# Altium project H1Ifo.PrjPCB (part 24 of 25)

## Sheet IfoSqz4B.SchDoc: D1800185
size C; Engineer: Daniel Sigg; DocumentNumber: 9; Revision: 4; SheetNumber: 9; SheetTotal: 10
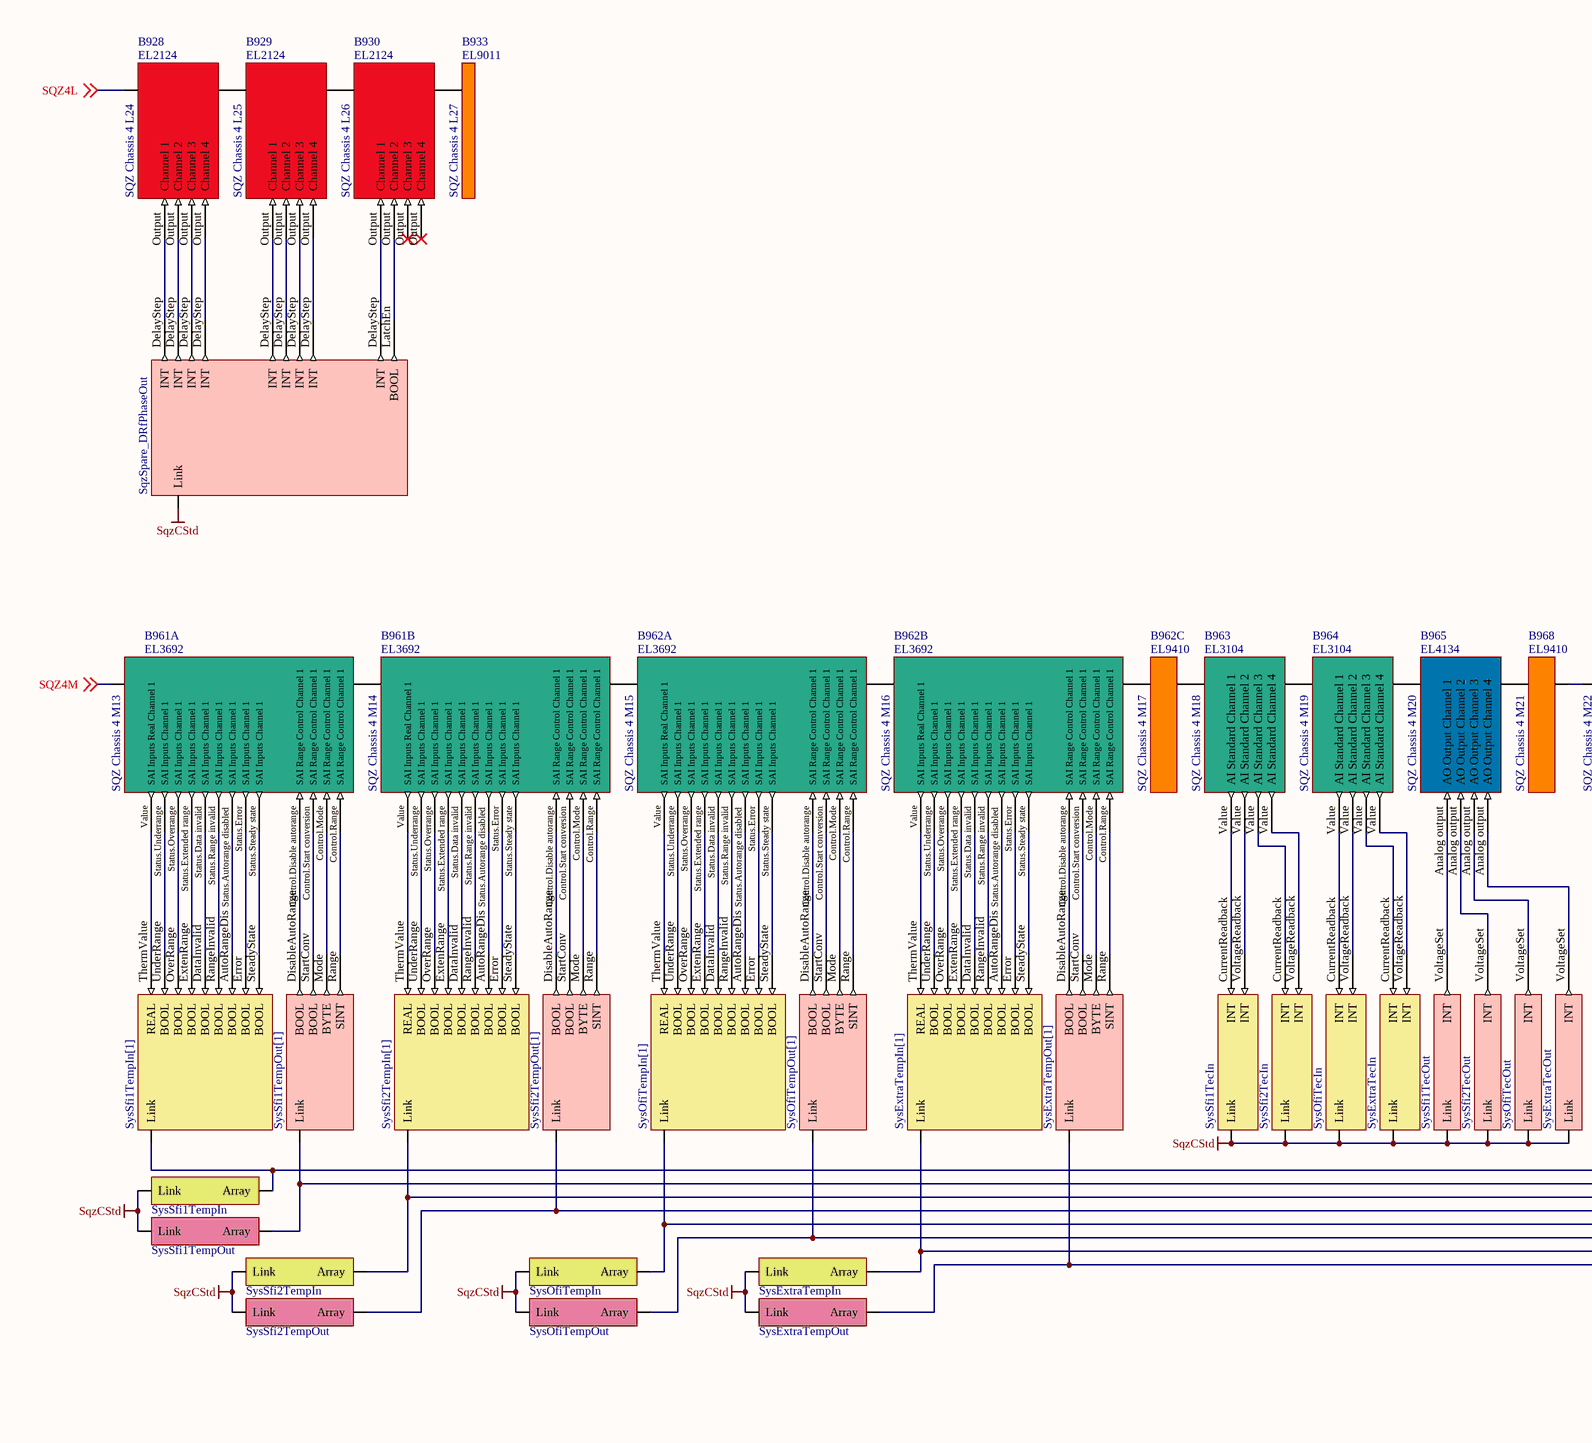
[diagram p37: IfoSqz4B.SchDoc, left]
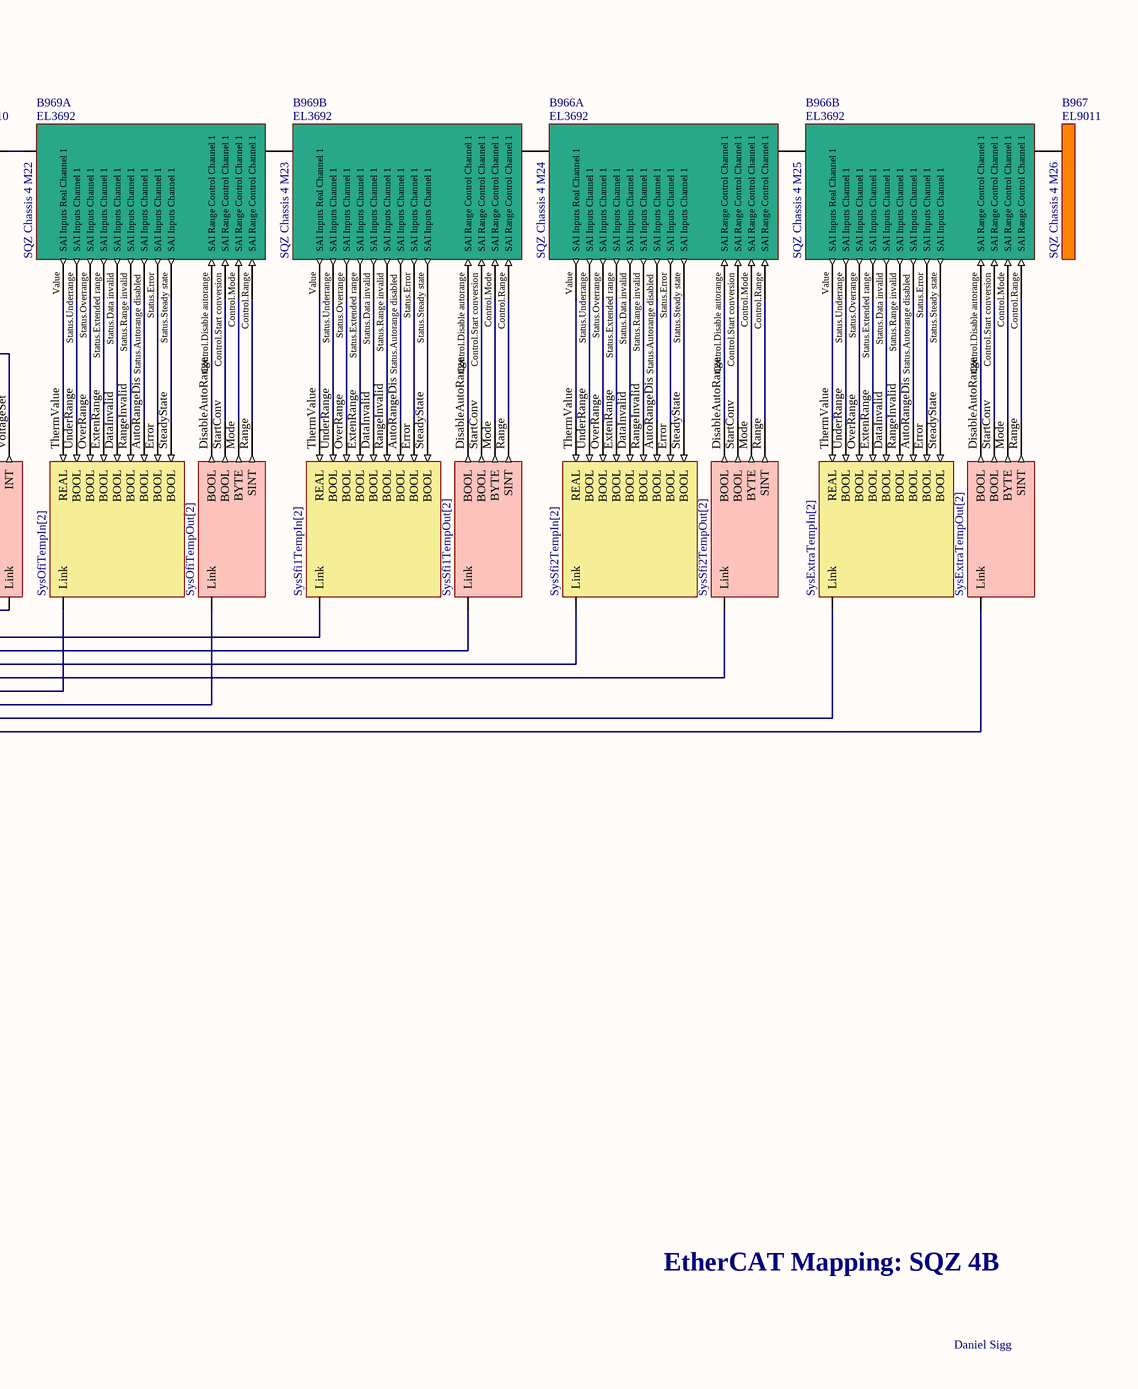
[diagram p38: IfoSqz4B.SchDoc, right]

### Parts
B928  SQZ Chassis 4 L24  Part Number: EL2124  (mechanical)
B929  SQZ Chassis 4 L25  Part Number: EL2124  (mechanical)
B930  SQZ Chassis 4 L26  Part Number: EL2124  (mechanical)
B933  SQZ Chassis 4 L27  Part Number: EL9011  (mechanical)
B961A  SQZ Chassis 4 M13  Part Number: EL3692  (mechanical)
B961B  SQZ Chassis 4 M14  Part Number: EL3692  (mechanical)
B962A  SQZ Chassis 4 M15  Part Number: EL3692  (mechanical)
B962B  SQZ Chassis 4 M16  Part Number: EL3692  (mechanical)
B962C  SQZ Chassis 4 M17  Part Number: EL9410  (mechanical)
B963  SQZ Chassis 4 M18  Part Number: EL3104  (mechanical)
B964  SQZ Chassis 4 M19  Part Number: EL3104  (mechanical)
B965  SQZ Chassis 4 M20  Part Number: EL4134  (mechanical)
B966A  SQZ Chassis 4 M24  Part Number: EL3692  (mechanical)
B966B  SQZ Chassis 4 M25  Part Number: EL3692  (mechanical)
B967  SQZ Chassis 4 M26  Part Number: EL9011  (mechanical)
B968  SQZ Chassis 4 M21  Part Number: EL9410  (mechanical)
B969A  SQZ Chassis 4 M22  Part Number: EL3692  (mechanical)
B969B  SQZ Chassis 4 M23  Part Number: EL3692  (mechanical)
V746  SqzSpare_DRfPhaseOut  (no BOM)
V750  SysOfiTempIn[2]  (no BOM)
V751  SysOfiTempOut[2]  (no BOM)
V752  SysSfi1TempIn[2]  (no BOM)
V753  SysSfi1TempOut[2]  (no BOM)
V754  SysOfiTempIn[1]  (no BOM)
V755  SysOfiTempOut[1]  (no BOM)
V756  SysSfi1TempIn[1]  (no BOM)
V757  SysSfi1TempOut[1]  (no BOM)
V758  SysSfi2TempIn[1]  (no BOM)
V759  SysSfi2TempOut[1]  (no BOM)
V760  SysExtraTempIn[1]  (no BOM)
V761  SysExtraTempOut[1]  (no BOM)
V762  SysOfiTecIn  (no BOM)
V763  SysSfi1TecIn  (no BOM)
V764  SysSfi2TecIn  (no BOM)
V765  SysExtraTecIn  (no BOM)
V766  SysOfiTecOut  (no BOM)
V767  SysSfi1TecOut  (no BOM)
V768  SysSfi2TecOut  (no BOM)
V769  SysExtraTecOut  (no BOM)
V770  SysSfi2TempIn[2]  (no BOM)
V771  SysSfi2TempOut[2]  (no BOM)
V772  SysExtraTempIn[2]  (no BOM)
V773  SysExtraTempOut[2]  (no BOM)
V788  SysOfiTempIn  (no BOM)
V789  SysOfiTempOut  (no BOM)
V790  SysSfi1TempIn  (no BOM)
V791  SysSfi2TempIn  (no BOM)
V792  SysExtraTempIn  (no BOM)
V793  SysSfi1TempOut  (no BOM)
V794  SysSfi2TempOut  (no BOM)
V795  SysExtraTempOut  (no BOM)

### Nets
SqzCStd: V746.?1(Link) V762.1(Link) V763.1(Link) V764.1(Link) V765.1(Link) V766.1(Link) V767.1(Link) V768.1(Link) V769.1(Link) V788.?1(Link) V789.?1(Link) V790.?1(Link) V791.?1(Link) V792.?1(Link) V793.?1(Link) V794.?1(Link) V795.?1(Link)
SQZ4L: B928.Ebus(A) ; off-sheet SQZ4L
SQZ4M: B961A.Ebus(A) ; off-sheet SQZ4M
NetB928_Ebus: B928.Ebus(B) B929.Ebus(A)
NetB928_Output: B928.Output(Channel_1) V746.DelayStep(INT)
NetB928_Output: B928.Output(Channel_2) V746.DelayStep(INT)  [a separate net that carries the same name]
NetB928_Output: B928.Output(Channel_3) V746.DelayStep(INT)  [a separate net that carries the same name]
NetB928_Output: B928.Output(Channel_4) V746.DelayStep(INT)  [a separate net that carries the same name]
NetB929_Ebus: B929.Ebus(B) B930.Ebus(A)
NetB929_Output: B929.Output(Channel_1) V746.DelayStep(INT)
NetB929_Output: B929.Output(Channel_2) V746.DelayStep(INT)  [a separate net that carries the same name]
NetB929_Output: B929.Output(Channel_3) V746.DelayStep(INT)  [a separate net that carries the same name]
NetB929_Output: B929.Output(Channel_4) V746.DelayStep(INT)  [a separate net that carries the same name]
NetB930_Ebus: B930.Ebus(B) B933.Ebus(A)
NetB930_Output: B930.Output(Channel_1) V746.DelayStep(INT)
NetB930_Output: B930.Output(Channel_2) V746.LatchEn(BOOL)  [a separate net that carries the same name]
NetB961A_Control.Disable autorange: B961A.Control.Disable_autorange(SAI_Range_Control_Channel_1) V757.DisableAutoRange(BOOL)
NetB961A_Control.Mode: B961A.Control.Mode(SAI_Range_Control_Channel_1) V757.Mode(BYTE)
NetB961A_Control.Range: B961A.Control.Range(SAI_Range_Control_Channel_1) V757.Range(SINT)
NetB961A_Control.Start conversion: B961A.Control.Start_conversion(SAI_Range_Control_Channel_1) V757.StartConv(BOOL)
NetB961A_Ebus: B961A.Ebus(B) B961B.Ebus(A)
NetB961A_Status.Autorange disabled: B961A.Status.Autorange_disabled(SAI_Inputs_Channel_1) V756.AutoRangeDis(BOOL)
NetB961A_Status.Data invalid: B961A.Status.Data_invalid(SAI_Inputs_Channel_1) V756.DataInvalid(BOOL)
NetB961A_Status.Error: B961A.Status.Error(SAI_Inputs_Channel_1) V756.Error(BOOL)
NetB961A_Status.Extended range: B961A.Status.Extended_range(SAI_Inputs_Channel_1) V756.ExtenRange(BOOL)
NetB961A_Status.Overrange: B961A.Status.Overrange(SAI_Inputs_Channel_1) V756.OverRange(BOOL)
NetB961A_Status.Range invalid: B961A.Status.Range_invalid(SAI_Inputs_Channel_1) V756.RangeInvalid(BOOL)
NetB961A_Status.Steady state: B961A.Status.Steady_state(SAI_Inputs_Channel_1) V756.SteadyState(BOOL)
NetB961A_Status.Underrange: B961A.Status.Underrange(SAI_Inputs_Channel_1) V756.UnderRange(BOOL)
NetB961A_Value: B961A.Value(SAI_Inputs_Real_Channel_1) V756.ThermValue(REAL)
NetB961B_Control.Disable autorange: B961B.Control.Disable_autorange(SAI_Range_Control_Channel_1) V759.DisableAutoRange(BOOL)
NetB961B_Control.Mode: B961B.Control.Mode(SAI_Range_Control_Channel_1) V759.Mode(BYTE)
NetB961B_Control.Range: B961B.Control.Range(SAI_Range_Control_Channel_1) V759.Range(SINT)
NetB961B_Control.Start conversion: B961B.Control.Start_conversion(SAI_Range_Control_Channel_1) V759.StartConv(BOOL)
NetB961B_Ebus: B961B.Ebus(B) B962A.Ebus(A)
NetB961B_Status.Autorange disabled: B961B.Status.Autorange_disabled(SAI_Inputs_Channel_1) V758.AutoRangeDis(BOOL)
NetB961B_Status.Data invalid: B961B.Status.Data_invalid(SAI_Inputs_Channel_1) V758.DataInvalid(BOOL)
NetB961B_Status.Error: B961B.Status.Error(SAI_Inputs_Channel_1) V758.Error(BOOL)
NetB961B_Status.Extended range: B961B.Status.Extended_range(SAI_Inputs_Channel_1) V758.ExtenRange(BOOL)
NetB961B_Status.Overrange: B961B.Status.Overrange(SAI_Inputs_Channel_1) V758.OverRange(BOOL)
NetB961B_Status.Range invalid: B961B.Status.Range_invalid(SAI_Inputs_Channel_1) V758.RangeInvalid(BOOL)
NetB961B_Status.Steady state: B961B.Status.Steady_state(SAI_Inputs_Channel_1) V758.SteadyState(BOOL)
NetB961B_Status.Underrange: B961B.Status.Underrange(SAI_Inputs_Channel_1) V758.UnderRange(BOOL)
NetB961B_Value: B961B.Value(SAI_Inputs_Real_Channel_1) V758.ThermValue(REAL)
NetB962A_Control.Disable autorange: B962A.Control.Disable_autorange(SAI_Range_Control_Channel_1) V755.DisableAutoRange(BOOL)
NetB962A_Control.Mode: B962A.Control.Mode(SAI_Range_Control_Channel_1) V755.Mode(BYTE)
NetB962A_Control.Range: B962A.Control.Range(SAI_Range_Control_Channel_1) V755.Range(SINT)
NetB962A_Control.Start conversion: B962A.Control.Start_conversion(SAI_Range_Control_Channel_1) V755.StartConv(BOOL)
NetB962A_Ebus: B962A.Ebus(B) B962B.Ebus(A)
NetB962A_Status.Autorange disabled: B962A.Status.Autorange_disabled(SAI_Inputs_Channel_1) V754.AutoRangeDis(BOOL)
NetB962A_Status.Data invalid: B962A.Status.Data_invalid(SAI_Inputs_Channel_1) V754.DataInvalid(BOOL)
NetB962A_Status.Error: B962A.Status.Error(SAI_Inputs_Channel_1) V754.Error(BOOL)
NetB962A_Status.Extended range: B962A.Status.Extended_range(SAI_Inputs_Channel_1) V754.ExtenRange(BOOL)
NetB962A_Status.Overrange: B962A.Status.Overrange(SAI_Inputs_Channel_1) V754.OverRange(BOOL)
NetB962A_Status.Range invalid: B962A.Status.Range_invalid(SAI_Inputs_Channel_1) V754.RangeInvalid(BOOL)
NetB962A_Status.Steady state: B962A.Status.Steady_state(SAI_Inputs_Channel_1) V754.SteadyState(BOOL)
NetB962A_Status.Underrange: B962A.Status.Underrange(SAI_Inputs_Channel_1) V754.UnderRange(BOOL)
NetB962A_Value: B962A.Value(SAI_Inputs_Real_Channel_1) V754.ThermValue(REAL)
NetB962B_Control.Disable autorange: B962B.Control.Disable_autorange(SAI_Range_Control_Channel_1) V761.DisableAutoRange(BOOL)
NetB962B_Control.Mode: B962B.Control.Mode(SAI_Range_Control_Channel_1) V761.Mode(BYTE)
NetB962B_Control.Range: B962B.Control.Range(SAI_Range_Control_Channel_1) V761.Range(SINT)
NetB962B_Control.Start conversion: B962B.Control.Start_conversion(SAI_Range_Control_Channel_1) V761.StartConv(BOOL)
NetB962B_Ebus: B962B.Ebus(B) B962C.Ebus(A)
NetB962B_Status.Autorange disabled: B962B.Status.Autorange_disabled(SAI_Inputs_Channel_1) V760.AutoRangeDis(BOOL)
NetB962B_Status.Data invalid: B962B.Status.Data_invalid(SAI_Inputs_Channel_1) V760.DataInvalid(BOOL)
NetB962B_Status.Error: B962B.Status.Error(SAI_Inputs_Channel_1) V760.Error(BOOL)
NetB962B_Status.Extended range: B962B.Status.Extended_range(SAI_Inputs_Channel_1) V760.ExtenRange(BOOL)
NetB962B_Status.Overrange: B962B.Status.Overrange(SAI_Inputs_Channel_1) V760.OverRange(BOOL)
NetB962B_Status.Range invalid: B962B.Status.Range_invalid(SAI_Inputs_Channel_1) V760.RangeInvalid(BOOL)
NetB962B_Status.Steady state: B962B.Status.Steady_state(SAI_Inputs_Channel_1) V760.SteadyState(BOOL)
NetB962B_Status.Underrange: B962B.Status.Underrange(SAI_Inputs_Channel_1) V760.UnderRange(BOOL)
NetB962B_Value: B962B.Value(SAI_Inputs_Real_Channel_1) V760.ThermValue(REAL)
NetB962C_Ebus: B962C.Ebus(B) B963.Ebus(A)
NetB963_Ebus: B963.Ebus(B) B964.Ebus(A)
NetB963_Value: B963.Value(AI_Standard_Channel_1) V763.CurrentReadback(INT)
NetB963_Value: B963.Value(AI_Standard_Channel_2) V763.VoltageReadback(INT)  [a separate net that carries the same name]
NetB963_Value: B963.Value(AI_Standard_Channel_3) V764.CurrentReadback(INT)  [a separate net that carries the same name]
NetB963_Value: B963.Value(AI_Standard_Channel_4) V764.VoltageReadback(INT)  [a separate net that carries the same name]
NetB964_Ebus: B964.Ebus(B) B965.Ebus(A)
NetB964_Value: B964.Value(AI_Standard_Channel_2) V762.VoltageReadback(INT)
NetB964_Value: B964.Value(AI_Standard_Channel_1) V762.CurrentReadback(INT)  [a separate net that carries the same name]
NetB964_Value: B964.Value(AI_Standard_Channel_3) V765.CurrentReadback(INT)  [a separate net that carries the same name]
NetB964_Value: B964.Value(AI_Standard_Channel_4) V765.VoltageReadback(INT)  [a separate net that carries the same name]
NetB965_Analog output: B965.Analog_output(AO_Output_Channel_1) V767.VoltageSet(INT)
NetB965_Analog output: B965.Analog_output(AO_Output_Channel_2) V768.VoltageSet(INT)  [a separate net that carries the same name]
NetB965_Analog output: B965.Analog_output(AO_Output_Channel_3) V766.VoltageSet(INT)  [a separate net that carries the same name]
NetB965_Analog output: B965.Analog_output(AO_Output_Channel_4) V769.VoltageSet(INT)  [a separate net that carries the same name]
NetB965_Ebus: B965.Ebus(B) B968.Ebus(A)
NetB966A_Control.Disable autorange: B966A.Control.Disable_autorange(SAI_Range_Control_Channel_1) V771.DisableAutoRange(BOOL)
NetB966A_Control.Mode: B966A.Control.Mode(SAI_Range_Control_Channel_1) V771.Mode(BYTE)
NetB966A_Control.Range: B966A.Control.Range(SAI_Range_Control_Channel_1) V771.Range(SINT)
NetB966A_Control.Start conversion: B966A.Control.Start_conversion(SAI_Range_Control_Channel_1) V771.StartConv(BOOL)
NetB966A_Ebus: B966A.Ebus(B) B966B.Ebus(A)
NetB966A_Ebus: B966A.Ebus(A) B969B.Ebus(B)  [a separate net that carries the same name]
NetB966A_Status.Autorange disabled: B966A.Status.Autorange_disabled(SAI_Inputs_Channel_1) V770.AutoRangeDis(BOOL)
NetB966A_Status.Data invalid: B966A.Status.Data_invalid(SAI_Inputs_Channel_1) V770.DataInvalid(BOOL)
NetB966A_Status.Error: B966A.Status.Error(SAI_Inputs_Channel_1) V770.Error(BOOL)
NetB966A_Status.Extended range: B966A.Status.Extended_range(SAI_Inputs_Channel_1) V770.ExtenRange(BOOL)
NetB966A_Status.Overrange: B966A.Status.Overrange(SAI_Inputs_Channel_1) V770.OverRange(BOOL)
NetB966A_Status.Range invalid: B966A.Status.Range_invalid(SAI_Inputs_Channel_1) V770.RangeInvalid(BOOL)
NetB966A_Status.Steady state: B966A.Status.Steady_state(SAI_Inputs_Channel_1) V770.SteadyState(BOOL)
NetB966A_Status.Underrange: B966A.Status.Underrange(SAI_Inputs_Channel_1) V770.UnderRange(BOOL)
NetB966A_Value: B966A.Value(SAI_Inputs_Real_Channel_1) V770.ThermValue(REAL)
NetB966B_Control.Disable autorange: B966B.Control.Disable_autorange(SAI_Range_Control_Channel_1) V773.DisableAutoRange(BOOL)
NetB966B_Control.Mode: B966B.Control.Mode(SAI_Range_Control_Channel_1) V773.Mode(BYTE)
NetB966B_Control.Range: B966B.Control.Range(SAI_Range_Control_Channel_1) V773.Range(SINT)
NetB966B_Control.Start conversion: B966B.Control.Start_conversion(SAI_Range_Control_Channel_1) V773.StartConv(BOOL)
NetB966B_Ebus: B966B.Ebus(B) B967.Ebus(A)
NetB966B_Status.Autorange disabled: B966B.Status.Autorange_disabled(SAI_Inputs_Channel_1) V772.AutoRangeDis(BOOL)
NetB966B_Status.Data invalid: B966B.Status.Data_invalid(SAI_Inputs_Channel_1) V772.DataInvalid(BOOL)
NetB966B_Status.Error: B966B.Status.Error(SAI_Inputs_Channel_1) V772.Error(BOOL)
NetB966B_Status.Extended range: B966B.Status.Extended_range(SAI_Inputs_Channel_1) V772.ExtenRange(BOOL)
NetB966B_Status.Overrange: B966B.Status.Overrange(SAI_Inputs_Channel_1) V772.OverRange(BOOL)
NetB966B_Status.Range invalid: B966B.Status.Range_invalid(SAI_Inputs_Channel_1) V772.RangeInvalid(BOOL)
NetB966B_Status.Steady state: B966B.Status.Steady_state(SAI_Inputs_Channel_1) V772.SteadyState(BOOL)
NetB966B_Status.Underrange: B966B.Status.Underrange(SAI_Inputs_Channel_1) V772.UnderRange(BOOL)
NetB966B_Value: B966B.Value(SAI_Inputs_Real_Channel_1) V772.ThermValue(REAL)
NetB968_Ebus: B968.Ebus(B) B969A.Ebus(A)
NetB969A_Control.Disable autorange: B969A.Control.Disable_autorange(SAI_Range_Control_Channel_1) V751.DisableAutoRange(BOOL)
NetB969A_Control.Mode: B969A.Control.Mode(SAI_Range_Control_Channel_1) V751.Mode(BYTE)
NetB969A_Control.Range: B969A.Control.Range(SAI_Range_Control_Channel_1) V751.Range(SINT)
NetB969A_Control.Start conversion: B969A.Control.Start_conversion(SAI_Range_Control_Channel_1) V751.StartConv(BOOL)
NetB969A_Ebus: B969A.Ebus(B) B969B.Ebus(A)
NetB969A_Status.Autorange disabled: B969A.Status.Autorange_disabled(SAI_Inputs_Channel_1) V750.AutoRangeDis(BOOL)
NetB969A_Status.Data invalid: B969A.Status.Data_invalid(SAI_Inputs_Channel_1) V750.DataInvalid(BOOL)
NetB969A_Status.Error: B969A.Status.Error(SAI_Inputs_Channel_1) V750.Error(BOOL)
NetB969A_Status.Extended range: B969A.Status.Extended_range(SAI_Inputs_Channel_1) V750.ExtenRange(BOOL)
NetB969A_Status.Overrange: B969A.Status.Overrange(SAI_Inputs_Channel_1) V750.OverRange(BOOL)
NetB969A_Status.Range invalid: B969A.Status.Range_invalid(SAI_Inputs_Channel_1) V750.RangeInvalid(BOOL)
NetB969A_Status.Steady state: B969A.Status.Steady_state(SAI_Inputs_Channel_1) V750.SteadyState(BOOL)
NetB969A_Status.Underrange: B969A.Status.Underrange(SAI_Inputs_Channel_1) V750.UnderRange(BOOL)
NetB969A_Value: B969A.Value(SAI_Inputs_Real_Channel_1) V750.ThermValue(REAL)
NetB969B_Control.Disable autorange: B969B.Control.Disable_autorange(SAI_Range_Control_Channel_1) V753.DisableAutoRange(BOOL)
NetB969B_Control.Mode: B969B.Control.Mode(SAI_Range_Control_Channel_1) V753.Mode(BYTE)
NetB969B_Control.Range: B969B.Control.Range(SAI_Range_Control_Channel_1) V753.Range(SINT)
NetB969B_Control.Start conversion: B969B.Control.Start_conversion(SAI_Range_Control_Channel_1) V753.StartConv(BOOL)
NetB969B_Status.Autorange disabled: B969B.Status.Autorange_disabled(SAI_Inputs_Channel_1) V752.AutoRangeDis(BOOL)
NetB969B_Status.Data invalid: B969B.Status.Data_invalid(SAI_Inputs_Channel_1) V752.DataInvalid(BOOL)
NetB969B_Status.Error: B969B.Status.Error(SAI_Inputs_Channel_1) V752.Error(BOOL)
NetB969B_Status.Extended range: B969B.Status.Extended_range(SAI_Inputs_Channel_1) V752.ExtenRange(BOOL)
NetB969B_Status.Overrange: B969B.Status.Overrange(SAI_Inputs_Channel_1) V752.OverRange(BOOL)
NetB969B_Status.Range invalid: B969B.Status.Range_invalid(SAI_Inputs_Channel_1) V752.RangeInvalid(BOOL)
NetB969B_Status.Steady state: B969B.Status.Steady_state(SAI_Inputs_Channel_1) V752.SteadyState(BOOL)
NetB969B_Status.Underrange: B969B.Status.Underrange(SAI_Inputs_Channel_1) V752.UnderRange(BOOL)
NetB969B_Value: B969B.Value(SAI_Inputs_Real_Channel_1) V752.ThermValue(REAL)
NetV750_1: V750.1(Link) V754.1(Link) V788.?2(Array)
NetV751_1: V751.1(Link) V755.1(Link) V789.?2(Array)
NetV752_1: V752.1(Link) V756.1(Link) V790.?2(Array)
NetV753_1: V753.1(Link) V757.1(Link) V793.?2(Array)
NetV758_1: V758.1(Link) V770.1(Link) V791.?2(Array)
NetV759_1: V759.1(Link) V771.1(Link) V794.?2(Array)
NetV760_1: V760.1(Link) V772.1(Link) V792.?2(Array)
NetV761_1: V761.1(Link) V773.1(Link) V795.?2(Array)

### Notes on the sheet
- EtherCAT Mapping: SQZ 4B
- Daniel Sigg

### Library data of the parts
B928 = TerminalEL2124: EtherCAT Terminal EL2124 4-chn Digital Ouput; Rail: Left; BoxNextB: OIWCCIRA; BoxPrev: IKRYUTNI; PortPrevFull: 1210/B; PortPrevShort: B; Fullname: TIID^Vertex Squeezer (EtherCAT)^SQZ Chassis 4 L0 (EK1101)^SQZ Chassis 4 L24 (EL2124); BoxAddr: 1211; Disabled: False
B929 = TerminalEL2124: EtherCAT Terminal EL2124 4-chn Digital Ouput; Rail: Left; BoxNextB: OJTEBPAB; BoxPrev: SBVBAHED; PortPrevFull: 1211/B; PortPrevShort: B; Fullname: TIID^Vertex Squeezer (EtherCAT)^SQZ Chassis 4 L0 (EK1101)^SQZ Chassis 4 L25 (EL2124); BoxAddr: 1212; Disabled: False
B930 = TerminalEL2124: EtherCAT Terminal EL2124 4-chn Digital Ouput; Rail: Left; BoxNextB: NRHBNLIL; BoxPrev: OIWCCIRA; PortPrevFull: 1212/B; PortPrevShort: B; Fullname: TIID^Vertex Squeezer (EtherCAT)^SQZ Chassis 4 L0 (EK1101)^SQZ Chassis 4 L26 (EL2124); BoxAddr: 1213; Disabled: False
B933 = TerminalEL9011: EtherCAT Terminal EL9011 End; BoxType: TerminalPassive; Rail: Left; BoxPrev: OJTEBPAB; PortPrevShort: B; Fullname: TIID^Vertex Squeezer (EtherCAT)^SQZ Chassis 4 L0 (EK1101)^SQZ Chassis 4 L27 (EL9011); Disabled: False
B961A = TerminalEL3692-1chn: EtherCAT Terminal EL3692 1-chn Resistance Measurement; Rail: Middle; BoxNextB: UBNVSPGB; BoxPrev: SXFJKERQ; PortPrevFull: 1226/B; PortPrevShort: B; Fullname: TIID^Vertex Squeezer (EtherCAT)^SQZ Chassis 4 M0 (EK1100)^SQZ Chassis 4 M13 (EL3692); BoxAddr: 1227; PDO Inputs: 0x1A00,0x1A02; PDO Outputs: 0x1600; Disabled: False
B961B = TerminalEL3692-1chn: EtherCAT Terminal EL3692 1-chn Resistance Measurement; Rail: Middle; BoxNextB: ALHVDIEX; BoxPrev: XCBOHHOF; PortPrevFull: 1227/B; PortPrevShort: B; Fullname: TIID^Vertex Squeezer (EtherCAT)^SQZ Chassis 4 M0 (EK1100)^SQZ Chassis 4 M14 (EL3692); BoxAddr: 1228; PDO Inputs: 0x1A00,0x1A02; PDO Outputs: 0x1600; Disabled: False
B962A = TerminalEL3692-1chn: EtherCAT Terminal EL3692 1-chn Resistance Measurement; Rail: Middle; BoxNextB: TFRQXLOH; BoxPrev: UBNVSPGB; PortPrevFull: 1228/B; PortPrevShort: B; Fullname: TIID^Vertex Squeezer (EtherCAT)^SQZ Chassis 4 M0 (EK1100)^SQZ Chassis 4 M15 (EL3692); BoxAddr: 1229; PDO Inputs: 0x1A00,0x1A02; PDO Outputs: 0x1600; Disabled: False
B962B = TerminalEL3692-1chn: EtherCAT Terminal EL3692 1-chn Resistance Measurement; Rail: Middle; BoxNextB: ZDXOLKQL; BoxPrev: ALHVDIEX; PortPrevFull: 1229/B; PortPrevShort: B; Fullname: TIID^Vertex Squeezer (EtherCAT)^SQZ Chassis 4 M0 (EK1100)^SQZ Chassis 4 M16 (EL3692); BoxAddr: 1230; PDO Inputs: 0x1A00,0x1A02; PDO Outputs: 0x1600; Disabled: False
B962C = TerminalEL9410: EtherCAT Terminal EL9410 Power; Rail: Middle; BoxNextB: POYUXNSI; BoxPrev: TFRQXLOH; PortPrevFull: 1230/B; PortPrevShort: B; Fullname: TIID^Vertex Squeezer (EtherCAT)^SQZ Chassis 4 M0 (EK1100)^SQZ Chassis 4 M17 (EL9410); BoxAddr: 1231; Disabled: False
B963 = TerminalEL3104: EtherCAT Terminal EL3104 4-chn Analog Input; Rail: Middle; BoxNextB: WNKQTDTO; BoxPrev: ZDXOLKQL; PortPrevFull: 1231/B; PortPrevShort: B; Fullname: TIID^Vertex Squeezer (EtherCAT)^SQZ Chassis 4 M0 (EK1100)^SQZ Chassis 4 M18 (EL3104); BoxAddr: 1232; Disabled: False
B964 = TerminalEL3104: EtherCAT Terminal EL3104 4-chn Analog Input; Rail: Middle; BoxNextB: MYVIGLKX; BoxPrev: POYUXNSI; PortPrevFull: 1232/B; PortPrevShort: B; Fullname: TIID^Vertex Squeezer (EtherCAT)^SQZ Chassis 4 M0 (EK1100)^SQZ Chassis 4 M19 (EL3104); BoxAddr: 1233; Disabled: False
B965 = TerminalEL4134: EtherCAT Terminal EL4134 4-chn Analog Ouput; Rail: Middle; BoxNextB: CVMEERUG; BoxPrev: WNKQTDTO; PortPrevFull: 1233/B; PortPrevShort: B; Fullname: TIID^Vertex Squeezer (EtherCAT)^SQZ Chassis 4 M0 (EK1100)^SQZ Chassis 4 M20 (EL4134); BoxAddr: 1234; Disabled: False
B966A = TerminalEL3692-1chn: EtherCAT Terminal EL3692 1-chn Resistance Measurement; Rail: Middle; BoxNextB: ACOCYMUJ; BoxPrev: CHKFXWZD; PortPrevFull: 1237/B; PortPrevShort: B; Fullname: TIID^Vertex Squeezer (EtherCAT)^SQZ Chassis 4 M0 (EK1100)^SQZ Chassis 4 M24 (EL3692); BoxAddr: 1238; PDO Inputs: 0x1A00,0x1A02; PDO Outputs: 0x1600; Disabled: False
B966B = TerminalEL3692-1chn: EtherCAT Terminal EL3692 1-chn Resistance Measurement; Rail: Middle; BoxNextB: OCCMWWTA; BoxPrev: CCHIHLWV; PortPrevFull: 1238/B; PortPrevShort: B; Fullname: TIID^Vertex Squeezer (EtherCAT)^SQZ Chassis 4 M0 (EK1100)^SQZ Chassis 4 M25 (EL3692); BoxAddr: 1239; PDO Inputs: 0x1A00,0x1A02; PDO Outputs: 0x1600; Disabled: False
B967 = TerminalEL9011: EtherCAT Terminal EL9011 End; BoxType: TerminalPassive; Rail: Middle; BoxPrev: ACOCYMUJ; PortPrevShort: B; Fullname: TIID^Vertex Squeezer (EtherCAT)^SQZ Chassis 4 M0 (EK1100)^SQZ Chassis 4 M26 (EL9011); Disabled: False
B968 = TerminalEL9410: EtherCAT Terminal EL9410 Power; Rail: Middle; BoxNextB: QXUBQGAJ; BoxPrev: MYVIGLKX; PortPrevFull: 1234/B; PortPrevShort: B; Fullname: TIID^Vertex Squeezer (EtherCAT)^SQZ Chassis 4 M0 (EK1100)^SQZ Chassis 4 M21 (EL9410); BoxAddr: 1235; Disabled: False
B969A = TerminalEL3692-1chn: EtherCAT Terminal EL3692 1-chn Resistance Measurement; Rail: Middle; BoxNextB: CHKFXWZD; BoxPrev: CVMEERUG; PortPrevFull: 1235/B; PortPrevShort: B; Fullname: TIID^Vertex Squeezer (EtherCAT)^SQZ Chassis 4 M0 (EK1100)^SQZ Chassis 4 M22 (EL3692); BoxAddr: 1236; PDO Inputs: 0x1A00,0x1A02; PDO Outputs: 0x1600; Disabled: False
B969B = TerminalEL3692-1chn: EtherCAT Terminal EL3692 1-chn Resistance Measurement; Rail: Middle; BoxNextB: CCHIHLWV; BoxPrev: QXUBQGAJ; PortPrevFull: 1236/B; PortPrevShort: B; Fullname: TIID^Vertex Squeezer (EtherCAT)^SQZ Chassis 4 M0 (EK1100)^SQZ Chassis 4 M23 (EL3692); BoxAddr: 1237; PDO Inputs: 0x1A00,0x1A02; PDO Outputs: 0x1600; Disabled: False
V746 = DelayLogic_DelayLogicOutStruct: DelayLogicOutStruct; BoxType: Variable; Instance: H1SqzCorner Instance; PLC: H1SqzCorner; Task: SqzCStd
V750 V752 V754 V756 V758 V760 V770 V772 = TECController_ThermistorInStruct: ThermistorInStruct; BoxType: Variable; Instance: H1SqzCorner Instance; PLC: H1SqzCorner; Task: SqzCStd
V751 V753 V755 V757 V759 V761 V771 V773 = TECController_ThermistorOutStruct: ThermistorOutStruct; BoxType: Variable; Instance: H1SqzCorner Instance; PLC: H1SqzCorner; Task: SqzCStd
V762-V765 = TECController_TECDriverInStruct: TECDriverInStruct; BoxType: Variable; Instance: H1SqzCorner Instance; PLC: H1SqzCorner; Task: SqzCStd
V766-V769 = TECController_TECDriverOutStruct: TECDriverOutStruct; BoxType: Variable; Instance: H1SqzCorner Instance; PLC: H1SqzCorner; Task: SqzCStd
V788 V790-V792 = ArrayAggregatorIn: Array [1..2] Of ThermistorInStruct; Instance: H1SqzCorner Instance; PLC: H1SqzCorner; Task: SqzCStd; Lower Bound: 1; Upper Bound: 2
V789 V793-V795 = ArrayAggregatorOut: Array [1..2] Of ThermistorOutStruct; Instance: H1SqzCorner Instance; PLC: H1SqzCorner; Task: SqzCStd; Lower Bound: 1; Upper Bound: 2

## Sheet IfoFcEnd.SchDoc: D1800185
size C; Engineer: Daniel Sigg; DocumentNumber: 8; Revision: 4; SheetNumber: 8; SheetTotal: 8
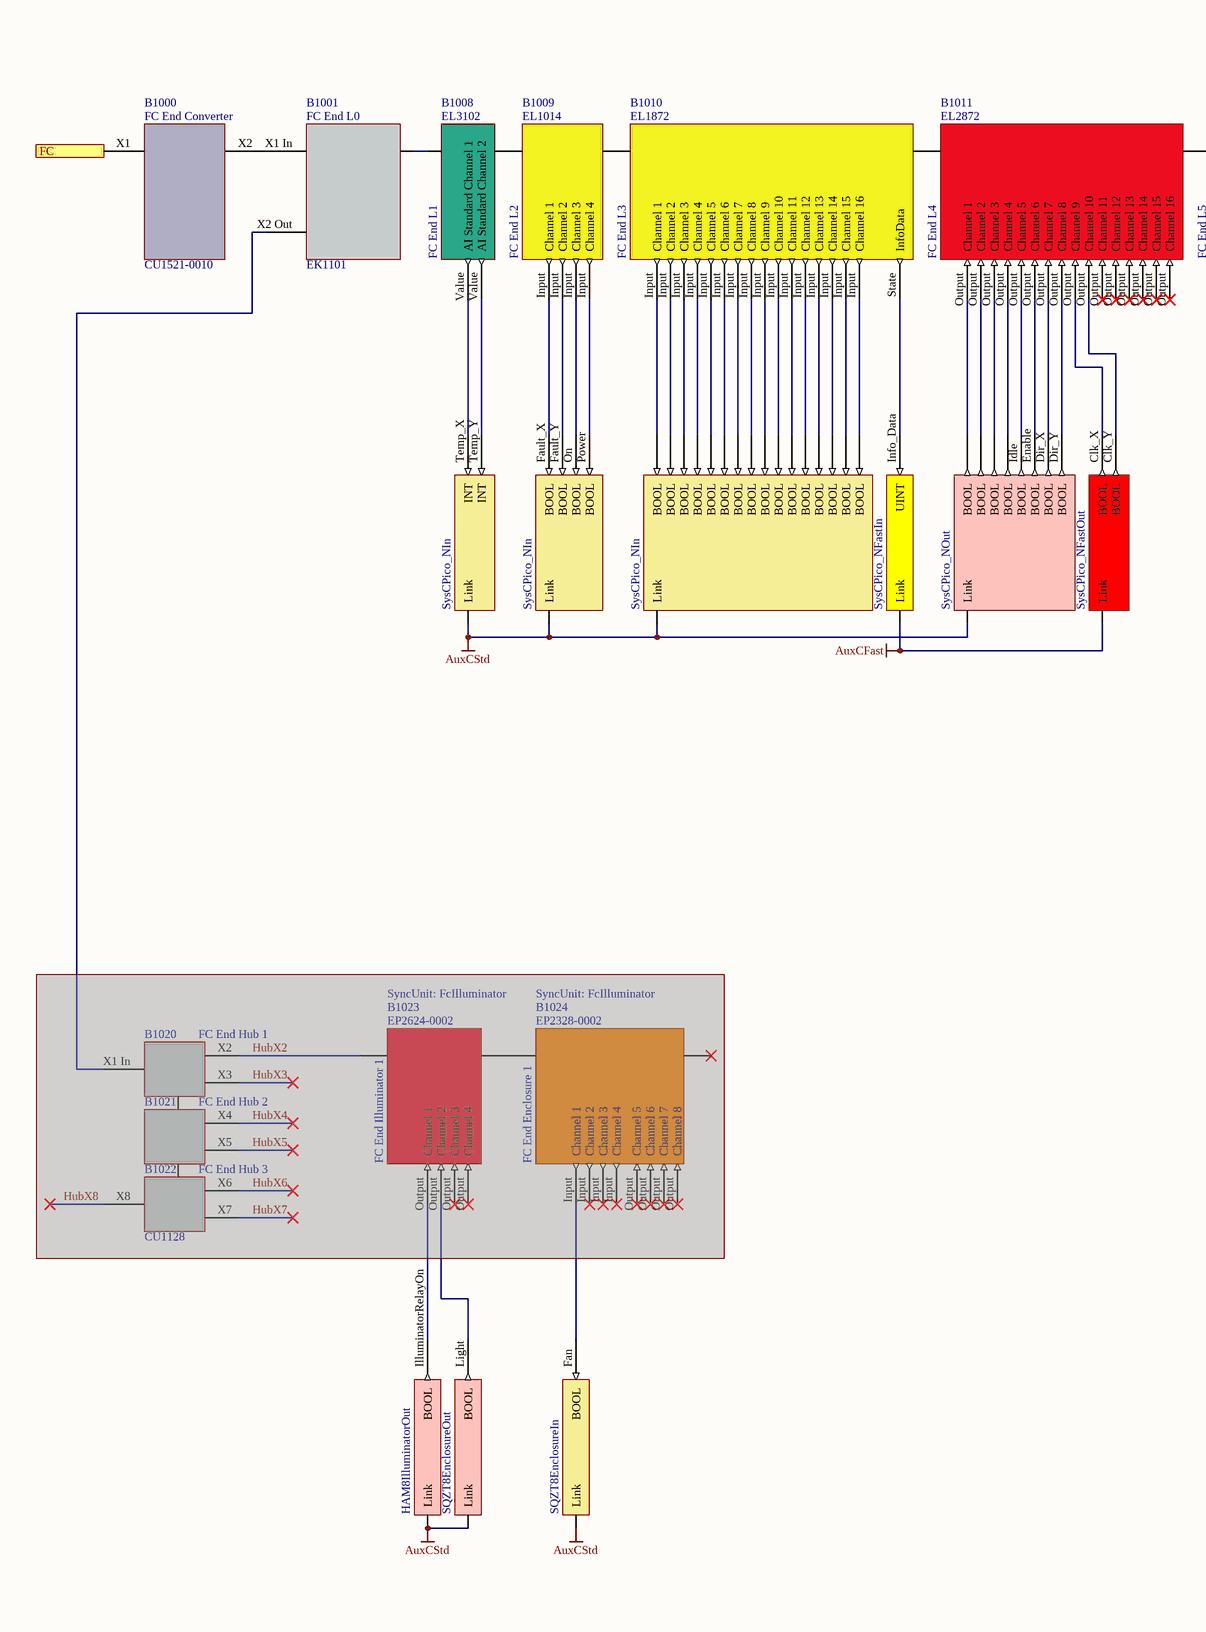
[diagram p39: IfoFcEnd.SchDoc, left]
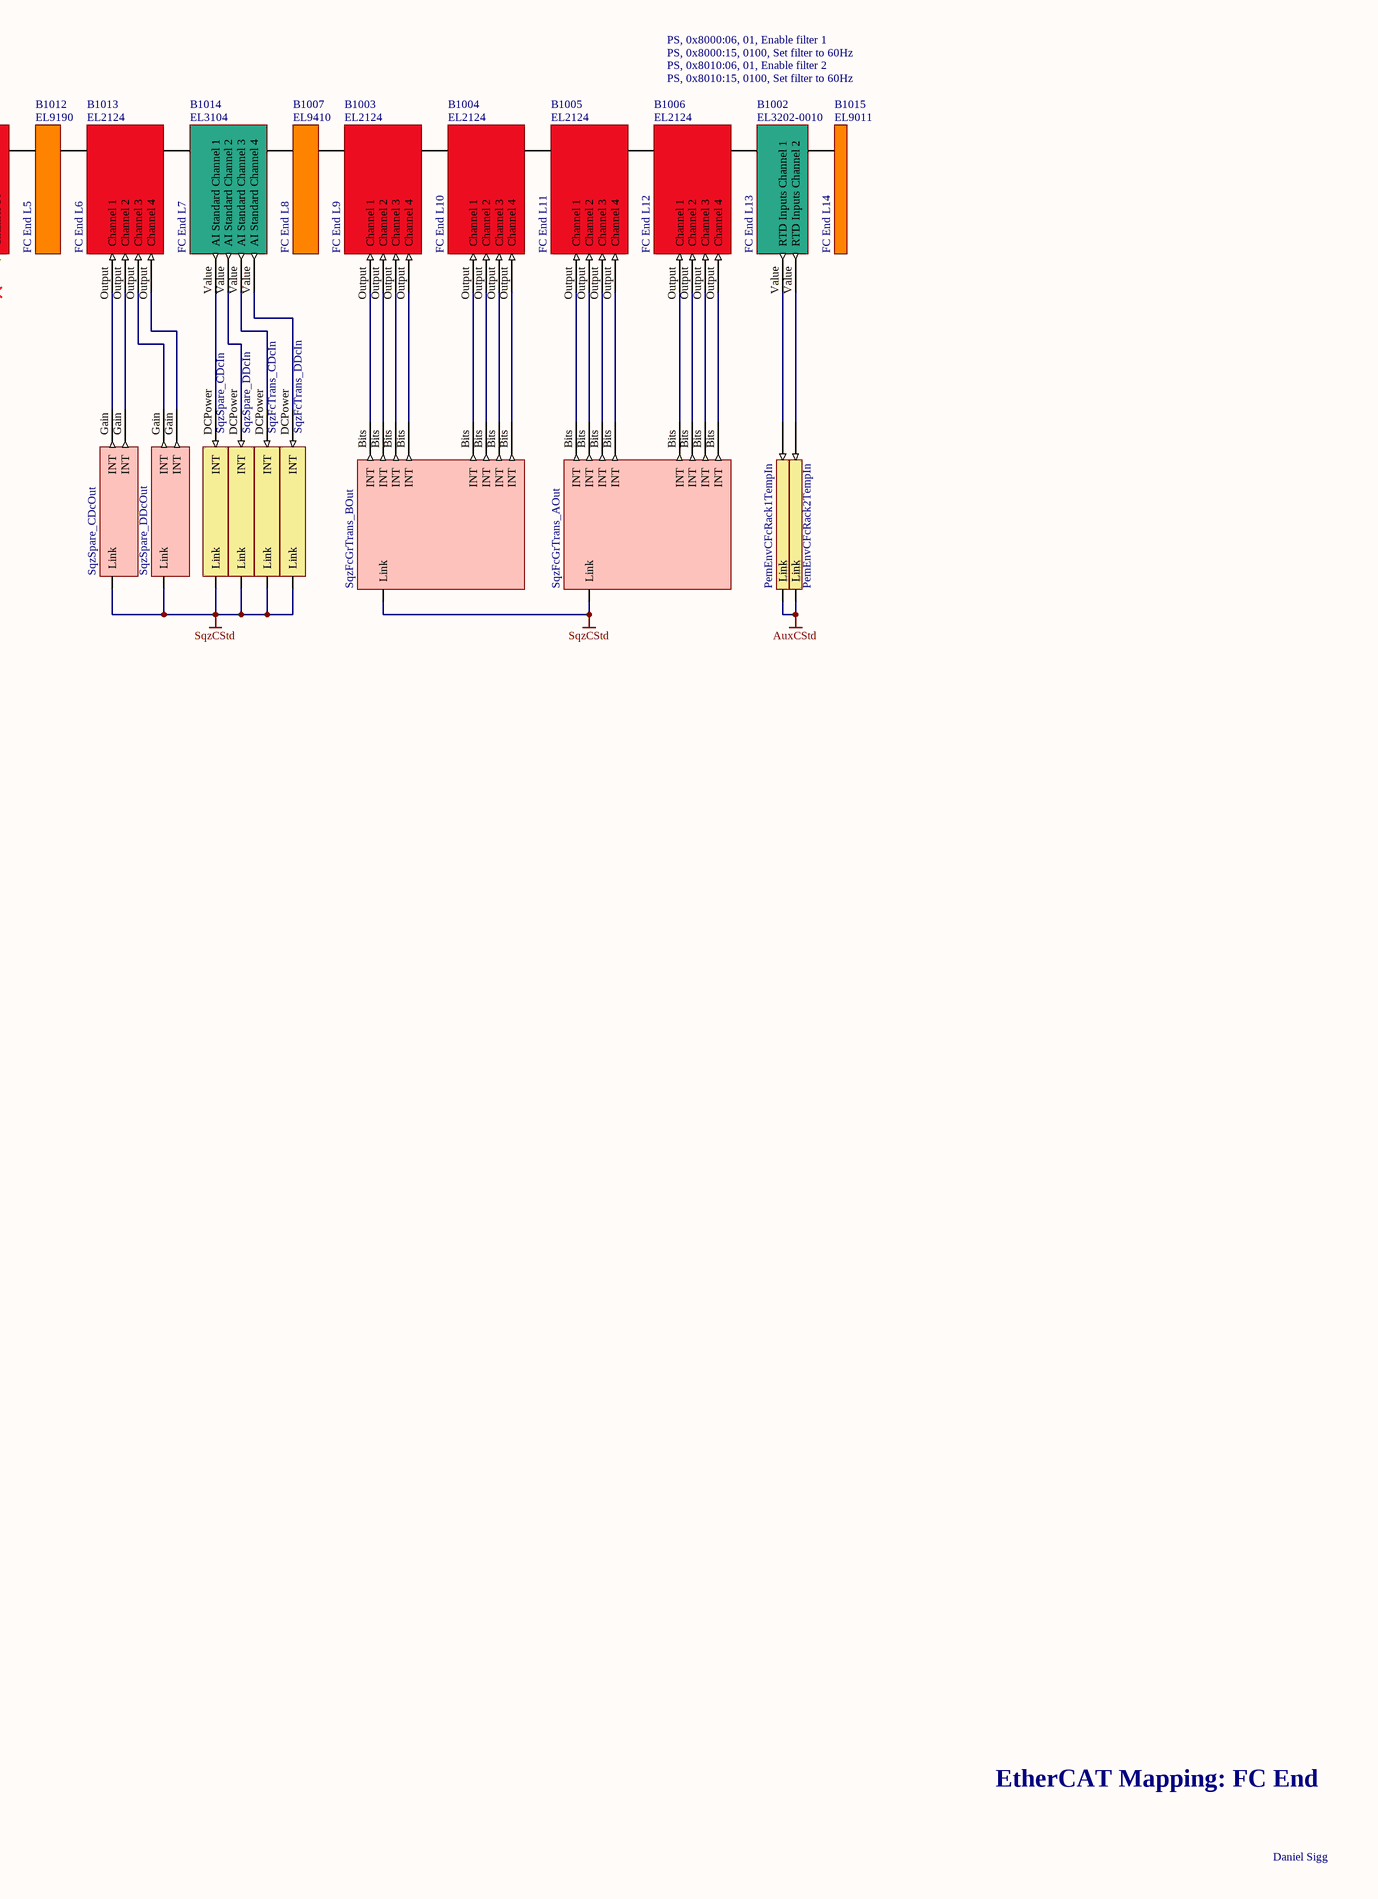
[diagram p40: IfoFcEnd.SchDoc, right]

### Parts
(Parts that share a designator on the sheet are numbered #1, #2 ... from top to bottom, then left to right.)
B1000  FC End Converter  Part Number: CU1521-0010  (mechanical)
B1001  FC End L0  Part Number: EK1101  (mechanical)
B1002  FC End L13  Part Number: EL3202-0010  Init0Cmd: PS, 0x8000:06, 01, Enable filter 1  Init1Cmd: PS, 0x8000:15, 0100, Set filter to 60Hz  Init2Cmd: PS, 0x8010:06, 01, Enable filter 2  Init3Cmd: PS, 0x8010:15, 0100, Set filter to 60Hz  (mechanical)
B1003  FC End L9  Part Number: EL2124  (mechanical)
B1004  FC End L10  Part Number: EL2124  (mechanical)
B1005  FC End L11  Part Number: EL2124  (mechanical)
B1006  FC End L12  Part Number: EL2124  (mechanical)
B1007  FC End L8  Part Number: EL9410  (mechanical)
B1008  FC End L1  Part Number: EL3102  (mechanical)
B1009  FC End L2  Part Number: EL1014  (mechanical)
B1010  FC End L3  Part Number: EL1872  (mechanical)
B1011  FC End L4  Part Number: EL2872  (mechanical)
B1012  FC End L5  Part Number: EL9190  (mechanical)
B1013  FC End L6  Part Number: EL2124  (mechanical)
B1014  FC End L7  Part Number: EL3104  (mechanical)
B1015  FC End L14  Part Number: EL9011  (mechanical)
B1020#2  FC End Hub 1  Part Number: CU1128  (mechanical)  (masked out: inside a compile mask, not in the netlist)
B1021#1  FC End Hub 2  (mechanical)  (masked out: inside a compile mask, not in the netlist)
B1022#1  FC End Hub 3  (mechanical)  (masked out: inside a compile mask, not in the netlist)
B1023#1  FC End Illuminator 1  Part Number: EP2624-0002  SyncUnit: FcIlluminator  (mechanical)  (masked out: inside a compile mask, not in the netlist)
B1024#1  FC End Enclosure 1  SyncUnit: FcIlluminator  Part Number: EP2328-0002  (mechanical)  (masked out: inside a compile mask, not in the netlist)
V850  PemEnvCFcRack1TempIn  (no BOM)
V851  PemEnvCFcRack2TempIn  (no BOM)
V852  SqzFcGrTrans_AOut  (no BOM)
V853  SqzFcGrTrans_BOut  (no BOM)
V854  SysCPico_NIn  (parts A,B,C of 3)  (no BOM)
V855  SysCPico_NFastIn  (no BOM)
V856  SysCPico_NOut  (no BOM)
V857  SysCPico_NFastOut  (no BOM)
V858  SqzSpare_CDcOut  (no BOM)
V859  SqzSpare_DDcOut  (no BOM)
V860  SqzSpare_CDcIn  (no BOM)
V861  SqzSpare_DDcIn  (no BOM)
V862  SqzFcTrans_CDcIn  (no BOM)
V863  SqzFcTrans_DDcIn  (no BOM)
V864  HAM8IlluminatorOut  (no BOM)
V865  SQZT8EnclosureOut  (no BOM)
V866  SQZT8EnclosureIn  (no BOM)

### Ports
FC

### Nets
AuxCFast: V855.0(Link) V857.0(Link)
AuxCStd: V850.?2(Link) V851.?2(Link) V854.0(Link) V854.1(Link) V854.2(Link) V856.0(Link) V864.0(Link) V865.?1(Link) V866.1(Link)
SqzCStd: V852.1(Link) V853.1(Link) V858.0(Link) V859.0(Link) V860.1(Link) V861.1(Link) V862.1(Link) V863.1(Link)
NetB1000_X1: B1000.X1(A) ; port FC
NetB1000_X2: B1000.X2(B) B1001.X1_In(A)
NetB1001_Ebus: B1001.Ebus(B) B1008.Ebus(A)
NetB1002_Ebus: B1002.Ebus(B) B1015.Ebus(A)
NetB1002_Ebus: B1002.Ebus(A) B1006.Ebus(B)  [a separate net that carries the same name]
NetB1002_Value: B1002.Value(RTD_Inputs_Channel_1) V850.?1
NetB1002_Value: B1002.Value(RTD_Inputs_Channel_2) V851.?1  [a separate net that carries the same name]
NetB1003_Ebus: B1003.Ebus(A) B1007.Ebus(B)
NetB1003_Ebus: B1003.Ebus(B) B1004.Ebus(A)  [a separate net that carries the same name]
NetB1003_Output: B1003.Output(Channel_1) V853.Bits(INT)
NetB1003_Output: B1003.Output(Channel_2) V853.Bits(INT)  [a separate net that carries the same name]
NetB1003_Output: B1003.Output(Channel_3) V853.Bits(INT)  [a separate net that carries the same name]
NetB1003_Output: B1003.Output(Channel_4) V853.Bits(INT)  [a separate net that carries the same name]
NetB1004_Ebus: B1004.Ebus(B) B1005.Ebus(A)
NetB1004_Output: B1004.Output(Channel_1) V853.Bits(INT)
NetB1004_Output: B1004.Output(Channel_2) V853.Bits(INT)  [a separate net that carries the same name]
NetB1004_Output: B1004.Output(Channel_3) V853.Bits(INT)  [a separate net that carries the same name]
NetB1004_Output: B1004.Output(Channel_4) V853.Bits(INT)  [a separate net that carries the same name]
NetB1005_Ebus: B1005.Ebus(B) B1006.Ebus(A)
NetB1005_Output: B1005.Output(Channel_1) V852.Bits(INT)
NetB1005_Output: B1005.Output(Channel_2) V852.Bits(INT)  [a separate net that carries the same name]
NetB1005_Output: B1005.Output(Channel_3) V852.Bits(INT)  [a separate net that carries the same name]
NetB1005_Output: B1005.Output(Channel_4) V852.Bits(INT)  [a separate net that carries the same name]
NetB1006_Output: B1006.Output(Channel_1) V852.Bits(INT)
NetB1006_Output: B1006.Output(Channel_2) V852.Bits(INT)  [a separate net that carries the same name]
NetB1006_Output: B1006.Output(Channel_3) V852.Bits(INT)  [a separate net that carries the same name]
NetB1006_Output: B1006.Output(Channel_4) V852.Bits(INT)  [a separate net that carries the same name]
NetB1007_Ebus: B1007.Ebus(A) B1014.Ebus(B)
NetB1008_Ebus: B1008.Ebus(B) B1009.Ebus(A)
NetB1008_Value: B1008.Value(AI_Standard_Channel_1) V854.Temp_X(INT)
NetB1008_Value: B1008.Value(AI_Standard_Channel_2) V854.Temp_Y(INT)  [a separate net that carries the same name]
NetB1009_Ebus: B1009.Ebus(B) B1010.Ebus(A)
NetB1009_Input: B1009.Input(Channel_1) V854.Fault_X(BOOL)
NetB1009_Input: B1009.Input(Channel_2) V854.Fault_Y(BOOL)  [a separate net that carries the same name]
NetB1009_Input: B1009.Input(Channel_3) V854.On(BOOL)  [a separate net that carries the same name]
NetB1009_Input: B1009.Input(Channel_4) V854.Power(BOOL)  [a separate net that carries the same name]
NetB1010_Ebus: B1010.Ebus(B) B1011.Ebus(A)
NetB1010_Input: B1010.Input(Channel_1) V854.MotorX1(BOOL)
NetB1010_Input: B1010.Input(Channel_2) V854.MotorX2(BOOL)  [a separate net that carries the same name]
NetB1010_Input: B1010.Input(Channel_3) V854.MotorX3(BOOL)  [a separate net that carries the same name]
NetB1010_Input: B1010.Input(Channel_4) V854.MotorX4(BOOL)  [a separate net that carries the same name]
NetB1010_Input: B1010.Input(Channel_5) V854.MotorX5(BOOL)  [a separate net that carries the same name]
NetB1010_Input: B1010.Input(Channel_6) V854.MotorX6(BOOL)  [a separate net that carries the same name]
NetB1010_Input: B1010.Input(Channel_7) V854.MotorX7(BOOL)  [a separate net that carries the same name]
NetB1010_Input: B1010.Input(Channel_8) V854.MotorX8(BOOL)  [a separate net that carries the same name]
NetB1010_Input: B1010.Input(Channel_9) V854.MotorY1(BOOL)  [a separate net that carries the same name]
NetB1010_Input: B1010.Input(Channel_10) V854.MotorY2(BOOL)  [a separate net that carries the same name]
NetB1010_Input: B1010.Input(Channel_11) V854.MotorY3(BOOL)  [a separate net that carries the same name]
NetB1010_Input: B1010.Input(Channel_12) V854.MotorY4(BOOL)  [a separate net that carries the same name]
NetB1010_Input: B1010.Input(Channel_13) V854.MotorY5(BOOL)  [a separate net that carries the same name]
NetB1010_Input: B1010.Input(Channel_14) V854.MotorY6(BOOL)  [a separate net that carries the same name]
NetB1010_Input: B1010.Input(Channel_15) V854.MotorY7(BOOL)  [a separate net that carries the same name]
NetB1010_Input: B1010.Input(Channel_16) V854.MotorY8(BOOL)  [a separate net that carries the same name]
NetB1010_State: B1010.State(InfoData) V855.Info_Data(UINT)
NetB1011_Ebus: B1011.Ebus(B) B1012.Ebus(A)
NetB1011_Output: B1011.Output(Channel_1) V856.MOTOR3(BOOL)
NetB1011_Output: B1011.Output(Channel_2) V856.MOTOR2(BOOL)  [a separate net that carries the same name]
NetB1011_Output: B1011.Output(Channel_3) V856.MOTOR1(BOOL)  [a separate net that carries the same name]
NetB1011_Output: B1011.Output(Channel_4) V856.MOTOR4(BOOL)  [a separate net that carries the same name]
NetB1011_Output: B1011.Output(Channel_5) V856.Idle(BOOL)  [a separate net that carries the same name]
NetB1011_Output: B1011.Output(Channel_6) V856.Enable(BOOL)  [a separate net that carries the same name]
NetB1011_Output: B1011.Output(Channel_7) V856.Dir_X(BOOL)  [a separate net that carries the same name]
NetB1011_Output: B1011.Output(Channel_8) V856.Dir_Y(BOOL)  [a separate net that carries the same name]
NetB1011_Output: B1011.Output(Channel_9) V857.Clk_X(BOOL)  [a separate net that carries the same name]
NetB1011_Output: B1011.Output(Channel_10) V857.Clk_Y(BOOL)  [a separate net that carries the same name]
NetB1012_Ebus: B1012.Ebus(B) B1013.Ebus(A)
NetB1013_Ebus: B1013.Ebus(B) B1014.Ebus(A)
NetB1013_Output: B1013.Output(Channel_1) V858.Gain(INT)
NetB1013_Output: B1013.Output(Channel_2) V858.Gain(INT)  [a separate net that carries the same name]
NetB1013_Output: B1013.Output(Channel_3) V859.Gain(INT)  [a separate net that carries the same name]
NetB1013_Output: B1013.Output(Channel_4) V859.Gain(INT)  [a separate net that carries the same name]
NetB1014_Value: B1014.Value(AI_Standard_Channel_1) V860.DCPower(INT)
NetB1014_Value: B1014.Value(AI_Standard_Channel_2) V861.DCPower(INT)  [a separate net that carries the same name]
NetB1014_Value: B1014.Value(AI_Standard_Channel_3) V862.DCPower(INT)  [a separate net that carries the same name]
NetB1014_Value: B1014.Value(AI_Standard_Channel_4) V863.DCPower(INT)  [a separate net that carries the same name]

Not connected (* = marked no-connect by the designer): B1001 X2 Out(C); V864 IlluminatorRelayOn(BOOL); V865 Light(BOOL); V866 Fan(BOOL)

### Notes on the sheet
- EtherCAT Mapping: FC End
- Daniel Sigg

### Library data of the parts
B1000 = MediaConverterFiberToCAT5: EtherCAT Media Converter; BoxType: Box; BoxNextB: WDMPTKSS; BoxPrev: TQXSIIBF; PortPrevFull: 1001/B; PortPrevShort: B 'X1'; Fullname: TIID^Filter Cavity End (EtherCAT)^FC End Converter (CU1521-0010); BoxAddr: 1002; Disabled: False
B1001 = CouplerEK1101: EtherCAT Coupler; Rail: Left; BoxNextB: HBGBFLEY; BoxPrev: PXLUFAHI; PortPrevFull: 1002/B; PortPrevShort: B 'X2'; Fullname: TIID^Filter Cavity End (EtherCAT)^FC End L0 (EK1101); BoxPorts: Junction; BoxAddr: 1003; Disabled: False
B1002 = TerminalEL3202-0010: EtherCAT Terminal EL3202-0010 2-chn Temperature Input; Rail: Left; BoxNextB: NWDBYSAB; BoxPrev: ULIEIJGL; PortPrevFull: 1014/B; PortPrevShort: B; Fullname: TIID^Filter Cavity End (EtherCAT)^FC End L0 (EK1101)^FC End L13 (EL3202-0010); BoxAddr: 1015; Disabled: False
B1003 = TerminalEL2124: EtherCAT Terminal EL2124 4-chn Digital Ouput; Rail: Left; BoxNextB: KHPMNFJU; BoxPrev: GXJCDOEX; PortPrevFull: 1010/B; PortPrevShort: B; Fullname: TIID^Filter Cavity End (EtherCAT)^FC End L0 (EK1101)^FC End L9 (EL2124); BoxAddr: 1011; Disabled: False
B1004 = TerminalEL2124: EtherCAT Terminal EL2124 4-chn Digital Ouput; Rail: Left; BoxNextB: HDSQIQHK; BoxPrev: VEPQEWPI; PortPrevFull: 1011/B; PortPrevShort: B; Fullname: TIID^Filter Cavity End (EtherCAT)^FC End L0 (EK1101)^FC End L10 (EL2124); BoxAddr: 1012; Disabled: False
B1005 = TerminalEL2124: EtherCAT Terminal EL2124 4-chn Digital Ouput; Rail: Left; BoxNextB: ULIEIJGL; BoxPrev: KHPMNFJU; PortPrevFull: 1012/B; PortPrevShort: B; Fullname: TIID^Filter Cavity End (EtherCAT)^FC End L0 (EK1101)^FC End L11 (EL2124); BoxAddr: 1013; Disabled: False
B1006 = TerminalEL2124: EtherCAT Terminal EL2124 4-chn Digital Ouput; Rail: Left; BoxNextB: DGBMPAWH; BoxPrev: HDSQIQHK; PortPrevFull: 1013/B; PortPrevShort: B; Fullname: TIID^Filter Cavity End (EtherCAT)^FC End L0 (EK1101)^FC End L12 (EL2124); BoxAddr: 1014; Disabled: False
B1007 = TerminalEL9410: EtherCAT Terminal EL9410 Power; Rail: Left; BoxNextB: VEPQEWPI; BoxPrev: MIBERBHY; PortPrevFull: 1009/B; PortPrevShort: B; Fullname: TIID^Filter Cavity End (EtherCAT)^FC End L0 (EK1101)^FC End L8 (EL9410); BoxAddr: 1010; Disabled: False
B1008 = TerminalEL3102: EtherCAT Terminal EL3102 2-chn Analog Input; Rail: Left; BoxNextB: OQWRSYUU; BoxPrev: WDMPTKSS; PortPrevFull: 1003/B; PortPrevShort: B; Fullname: TIID^Filter Cavity End (EtherCAT)^FC End L0 (EK1101)^FC End L1 (EL3102); BoxAddr: 1004; Disabled: False
B1009 = TerminalEL1014: EtherCAT Terminal EL1014 4-channel digital input terminal 24 V DC; Rail: Left; BoxNextB: DUXXGMSK; BoxPrev: HBGBFLEY; PortPrevFull: 1004/B; PortPrevShort: B; Fullname: TIID^Filter Cavity End (EtherCAT)^FC End L0 (EK1101)^FC End L2 (EL1014); BoxAddr: 1005; Disabled: False
B1010 = TerminalEL1872InfoData: EtherCAT Terminal EL1872 16-channel digital input terminal 24 V DC; Rail: Left; BoxNextB: CAWBPIQN; BoxPrev: OQWRSYUU; PortPrevFull: 1005/B; PortPrevShort: B; Fullname: TIID^Filter Cavity End (EtherCAT)^FC End L0 (EK1101)^FC End L3 (EL1872); BoxAddr: 1006; Disabled: False
B1011 = TerminalEL2872: EtherCAT Terminal EL2872 16-channel digital output terminal 24 V DC; Rail: Left; BoxNextB: RPYCVFHE; BoxPrev: DUXXGMSK; PortPrevFull: 1006/B; PortPrevShort: B; Fullname: TIID^Filter Cavity End (EtherCAT)^FC End L0 (EK1101)^FC End L4 (EL2872); BoxAddr: 1007; Disabled: False
B1012 = TerminalEL9190: EtherCAT Terminal EL9190 Supply; BoxType: TerminalPassive; Rail: Left; BoxNextB: WHVQWLXF; BoxPrev: CAWBPIQN; PortPrevShort: B; Fullname: TIID^Filter Cavity End (EtherCAT)^FC End L0 (EK1101)^FC End L5 (EL9190); Disabled: False
B1013 = TerminalEL2124: EtherCAT Terminal EL2124 4-chn Digital Ouput; Rail: Left; BoxNextB: MIBERBHY; BoxPrev: RPYCVFHE; PortPrevFull: 1007/B; PortPrevShort: B; Fullname: TIID^Filter Cavity End (EtherCAT)^FC End L0 (EK1101)^FC End L6 (EL2124); BoxAddr: 1008; Disabled: False
B1014 = TerminalEL3104: EtherCAT Terminal EL3104 4-chn Analog Input; Rail: Left; BoxNextB: GXJCDOEX; BoxPrev: WHVQWLXF; PortPrevFull: 1008/B; PortPrevShort: B; Fullname: TIID^Filter Cavity End (EtherCAT)^FC End L0 (EK1101)^FC End L7 (EL3104); BoxAddr: 1009; Disabled: False
B1015 = TerminalEL9011: EtherCAT Terminal EL9011 End; BoxType: TerminalPassive; Rail: Left; BoxPrev: DGBMPAWH; PortPrevShort: B; Fullname: TIID^Filter Cavity End (EtherCAT)^FC End L0 (EK1101)^FC End L14 (EL9011); Disabled: False
B1020#2 = HubCU1128: EtherCAT Hub; BoxType: Box; BoxPorts: Junction; Disabled: False
B1021#1 = HubCU1128-B: EtherCAT Hub subpart B; Part Number: CU1128-0001; BoxType: Box; BoxPorts: Junction; Disabled: False
B1022#1 = HubCU1128-C: EtherCAT Hub subpart C; Part Number: CU1128-0002; BoxType: Box; BoxPorts: Junction; Disabled: False
B1023#1 = BoxEP2624-0002: EtherCAT Box EP2624-0002 4-channel relay output 25 V AC/30 V DC; Disabled: False
B1024#1 = BoxEP2328-0002: EtherCAT Box EP2328-0002 4 x digital input and 4 x digital output 24 V DC; Disabled: False
V850 V851 = VariableInINT: INT; PLC: H1AuxCorner; Task: AuxCStd; Instance: H1AuxCorner Instance
V852 V853 = IscWhitening_WhiteningBitsOutStruct: WhiteningBitsOutStruct; BoxType: Variable; Instance: H1SqzCorner Instance; PLC: H1SqzCorner; Task: SqzCStd
V854 = Picomotor_PicomotorInStruct: PicomotorInStruct; BoxType: Variable; Instance: H1AuxCorner Instance; PLC: H1AuxCorner; Task: AuxCStd
V855 = Picomotor_PicomotorFastInStruct: PicomotorFastInStruct; BoxType: Variable; Instance: H1AuxCorner Instance; PLC: H1AuxCorner; Task: AuxCFast
V856 = Picomotor_PicomotorOutStruct: PicomotorOutStruct; BoxType: Variable; Instance: H1AuxCorner Instance; PLC: H1AuxCorner; Task: AuxCStd
V857 = Picomotor_PicomotorFastOutStruct: PicomotorFastOutStruct; BoxType: Variable; Instance: H1AuxCorner Instance; PLC: H1AuxCorner; Task: AuxCFast
V858 V859 = DCPower_DCPowerOutStruct: DCPowerOutStruct; BoxType: Variable; Instance: H1SqzCorner Instance; PLC: H1SqzCorner; Task: SqzCStd
V860-V863 = DCPower_DCPowerInStruct: DCPowerInStruct; BoxType: Variable; Instance: H1SqzCorner Instance; PLC: H1SqzCorner; Task: SqzCStd
V864 = Illuminator_IlluminatorOutStruct: IlluminatorOutStruct; BoxType: Variable; Instance: H1AuxCorner Instance; PLC: H1AuxCorner; Task: AuxCStd
V865 = Enclosure_EnclosureOutStruct: EnclosureOutStruct; BoxType: Variable; Instance: H1AuxCorner Instance; PLC: H1AuxCorner; Task: AuxCStd
V866 = Enclosure_EnclosureInStruct: EnclosureInStruct; BoxType: Variable; Instance: H1AuxCorner Instance; PLC: H1AuxCorner; Task: AuxCStd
